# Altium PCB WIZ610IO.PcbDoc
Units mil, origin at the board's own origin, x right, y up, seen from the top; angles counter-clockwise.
Board outline 905.51 x 984.25 mil, 4 copper layers (Top Layer, MidLayer1, Mid-Layer 2, Bottom Layer); 42 components, 42 nets, 155 pads, 63 vias.
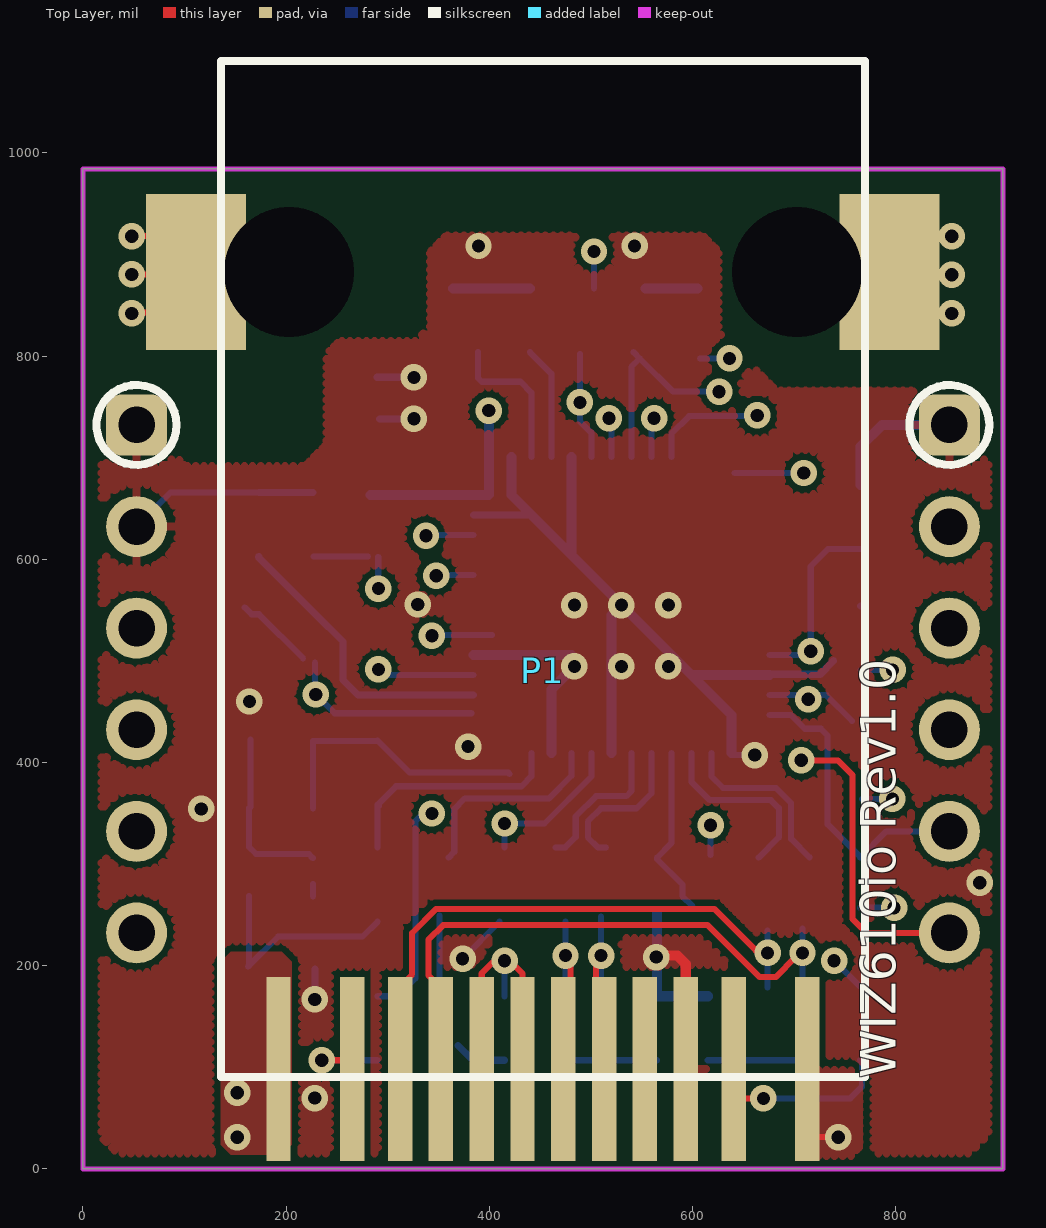
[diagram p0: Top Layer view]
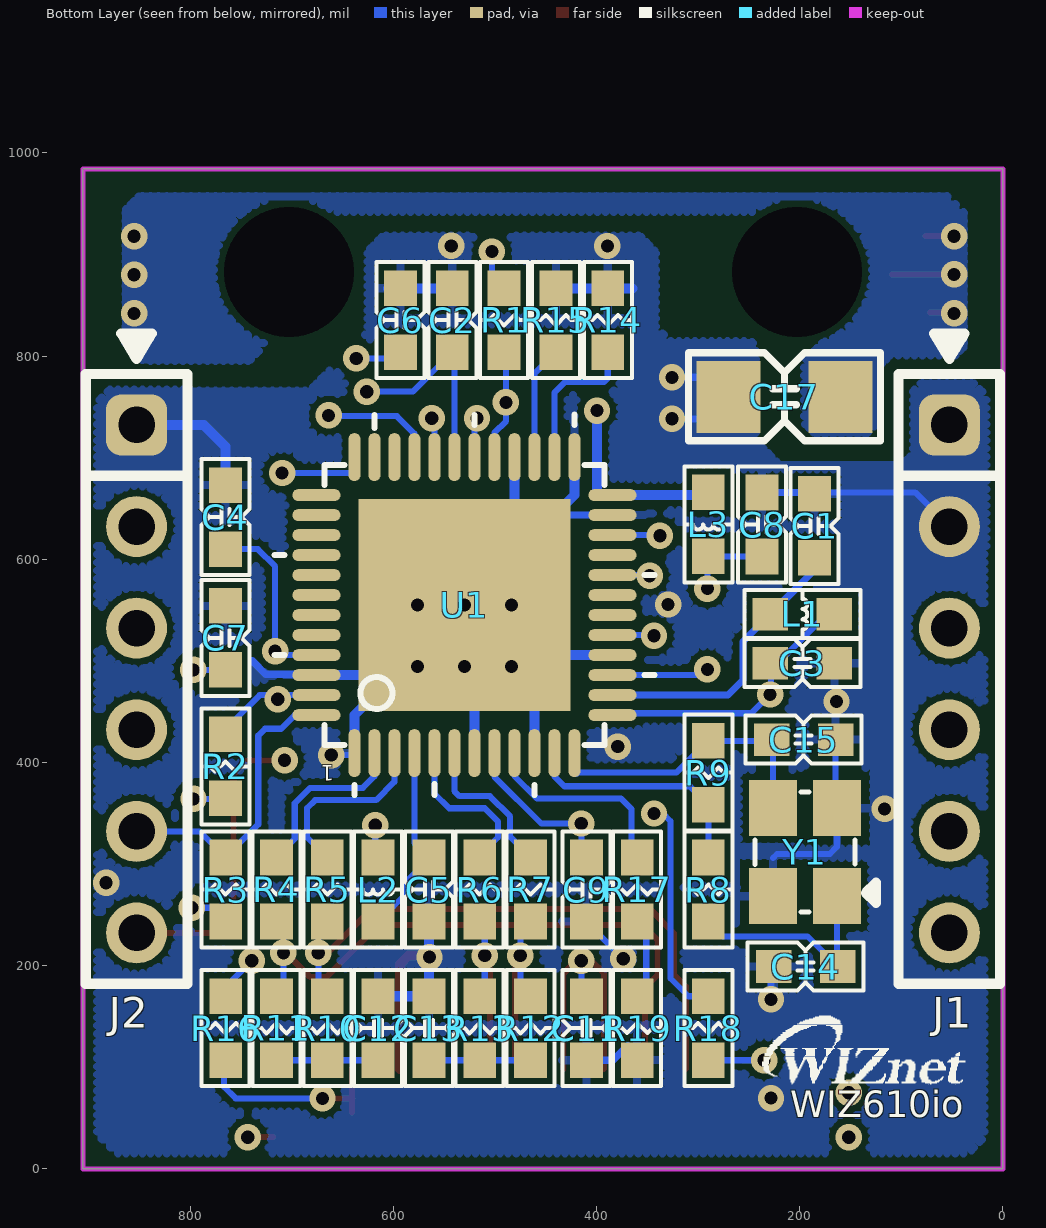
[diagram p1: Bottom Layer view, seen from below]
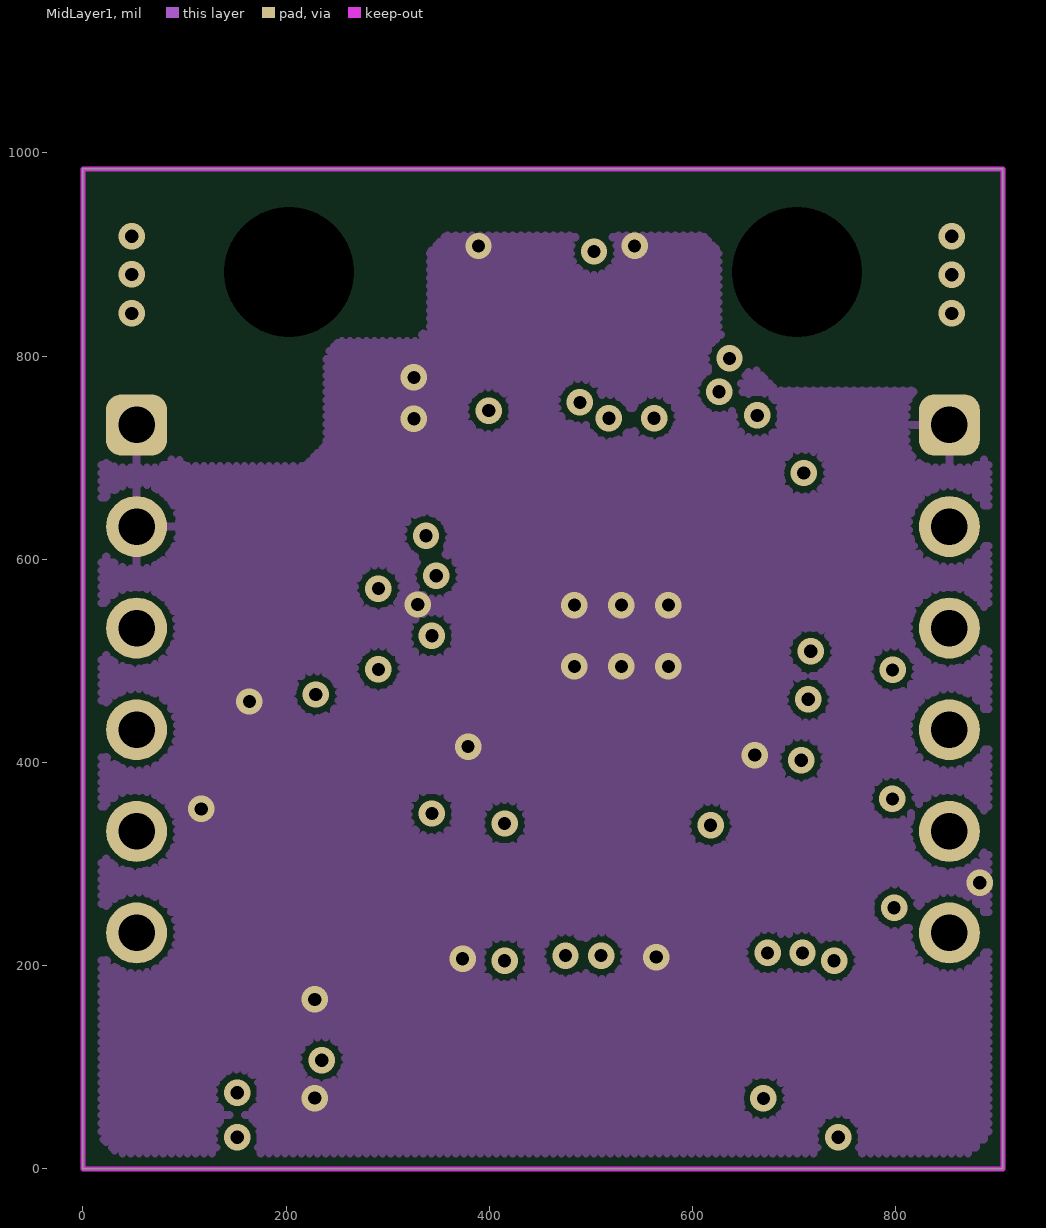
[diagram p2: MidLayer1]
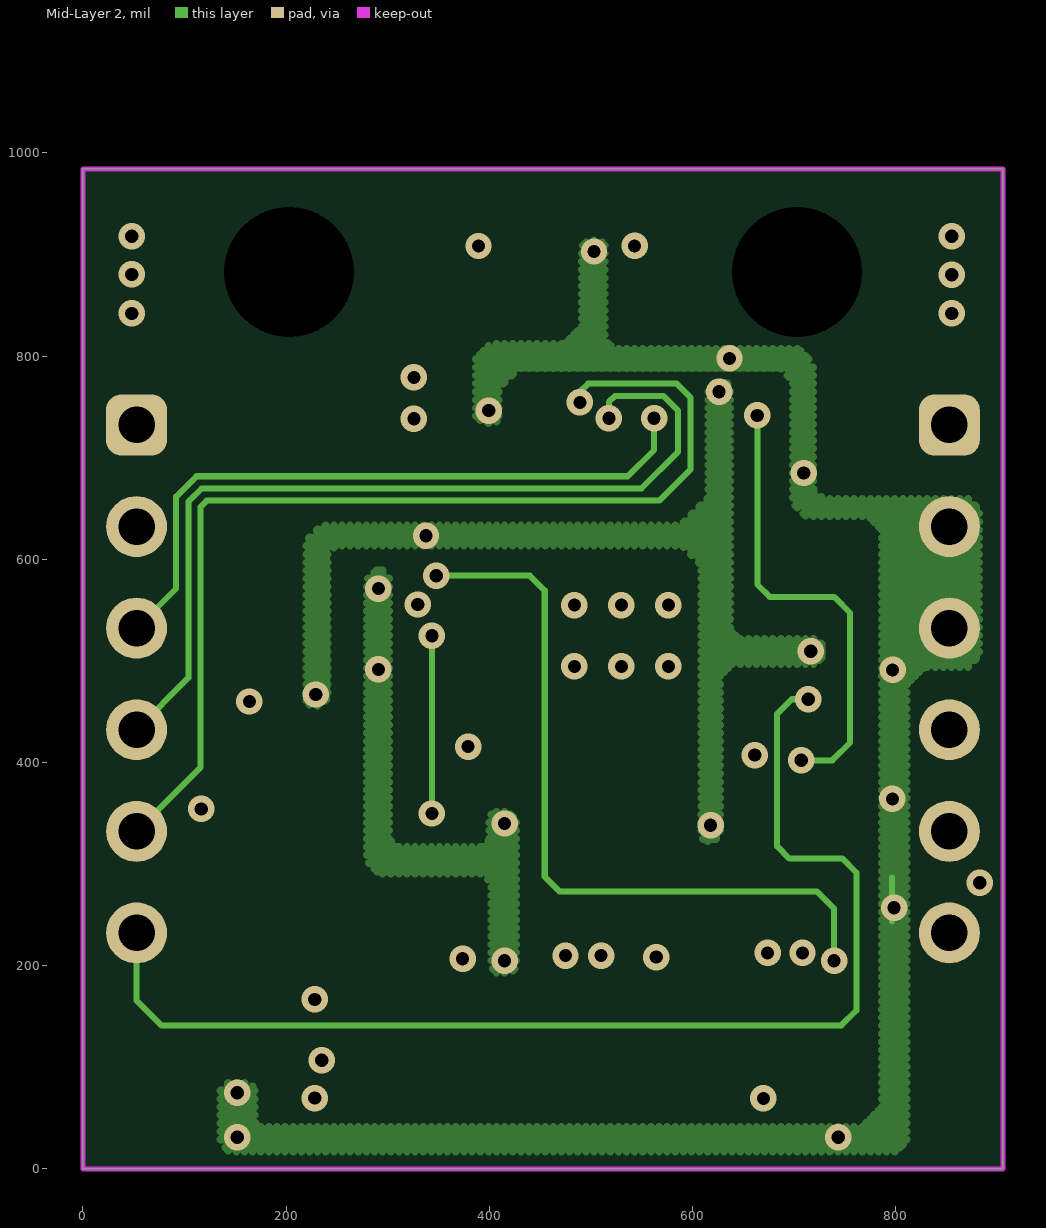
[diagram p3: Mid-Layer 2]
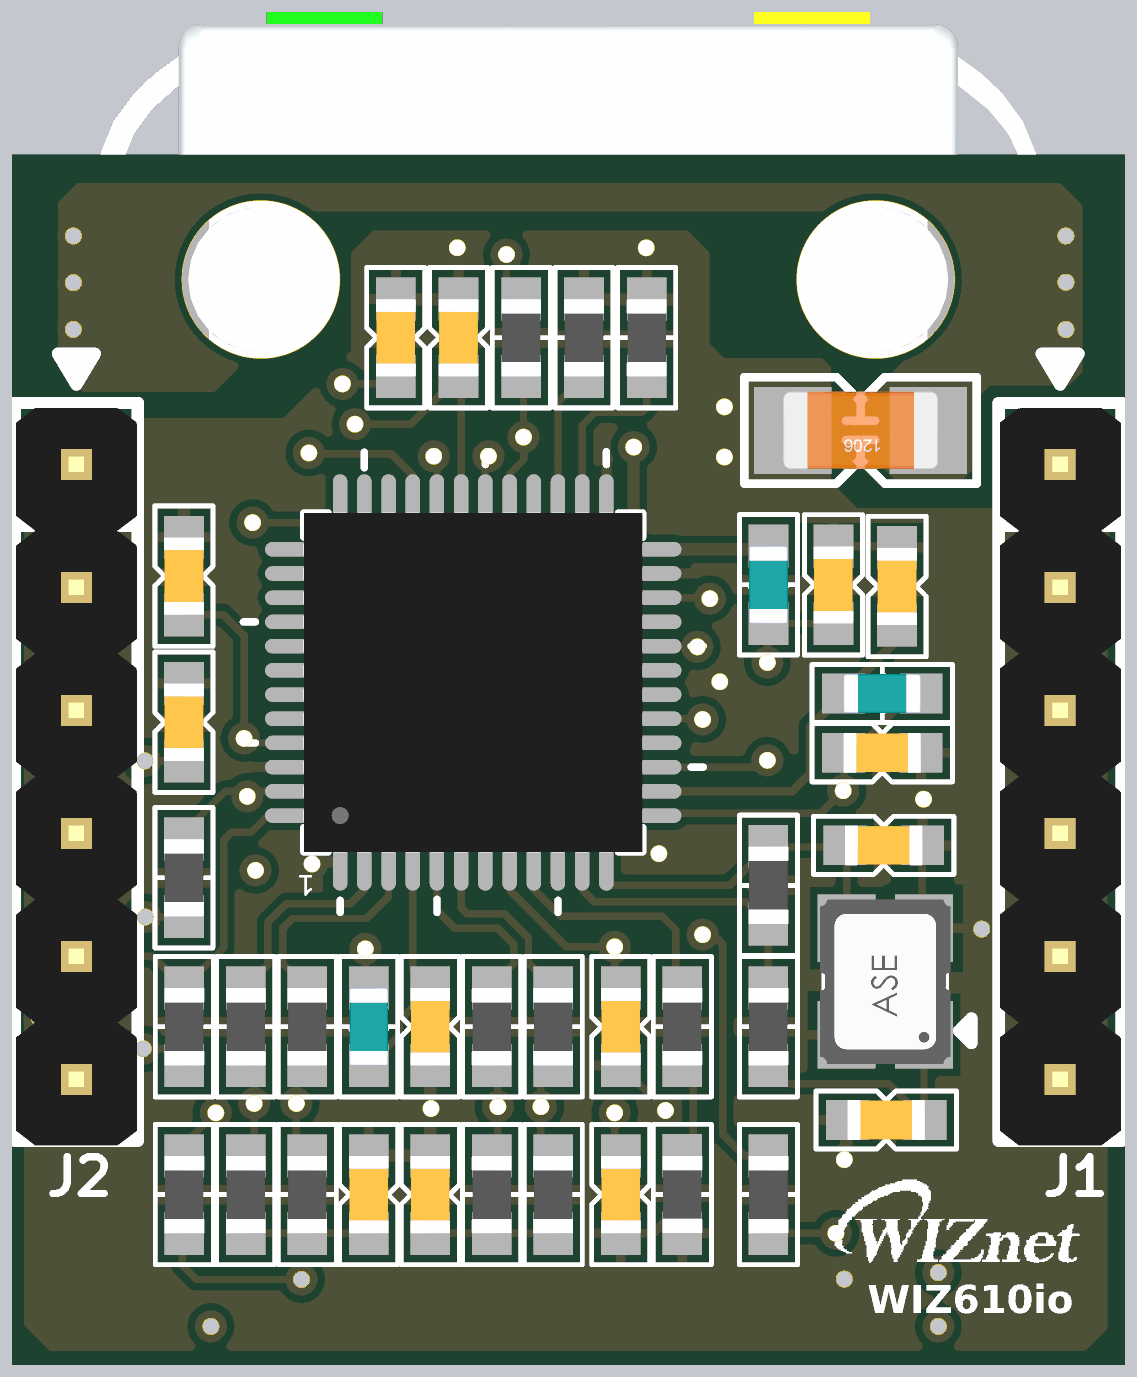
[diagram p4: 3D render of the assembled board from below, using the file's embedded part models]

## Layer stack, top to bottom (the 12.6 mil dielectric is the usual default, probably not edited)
Top Layer: signal copper 1.4
Dielectric: core 12.6, FR-4, Dk 4.8
MidLayer1: signal copper 1.4
Dielectric: prepreg 12.6, FR-4, Dk 4.8
Mid-Layer 2: signal copper 1.4
Dielectric: core 12.6, FR-4, Dk 4.8
Bottom Layer: signal copper 1.4

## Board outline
0,0 905.51,0 905.51,984.25 0,984.25

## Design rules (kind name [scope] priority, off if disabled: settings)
Clearance [All] p1: gap=6
DiffPairsRouting [All] p1: maxlimit=10 minlimit=10 mostfreqgap=10 maxuncoupledlength=500
PlaneClearance [All] p1: clearance=12
PlaneConnect [All] p1: planeconnectstyle=Direct reliefexpansion=20 reliefentries=4 reliefconductorwidth=10 reliefairgap=10
PolygonConnect PolygonConnect_1 [IsVia] p1: connectstyle=Direct reliefconductorwidth=10 reliefentries=4 polygonreliefangle="90 Angle" airgapwidth=10
PolygonConnect [All] p2: connectstyle=Relief reliefconductorwidth=8 reliefentries=4 polygonreliefangle="90 Angle" airgapwidth=8
RoutingVias [All] p1: holewidth=12 width=20 viastyle="Through Hole" minholewidth=12 minwidth=20 maxholewidth=28 maxwidth=50
SolderMaskExpansion [All] p1: expansion=0
Width [All] p1: maxlimit=100 minlimit=4 preferedwidth=10
25 further rules are at their usual default settings.

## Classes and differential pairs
differential pair RXO: +RXO_P -RXO_N
differential pair TXO: +TXO_P -TXO_N

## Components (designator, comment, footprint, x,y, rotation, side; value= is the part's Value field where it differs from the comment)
C1 "100nF" 0603-C 185.37,633.04 r270 bottom
C2 "100nF" 0603-C 541.97,835.34 r270 bottom
C3 "100nF" 0603-C 197.46,497.78 r0 bottom
C4 "100nF" 0603-C 765.31,641.51 r270 bottom
C5 "100nF" 0603-C 565,275 r90 bottom
C6 "100nF" 0603-C 592.97,835.34 r270 bottom
C7 "100nF" 0603-C 765.31,522.68 r270 bottom
C8 "100nF" 0603-C 237.11,634.28 r270 bottom
C9 "100nF" 0603-C 410,275 r90 bottom
C11 "1uF" 0603-C 410,138.5 r90 bottom
C12 "100nF" 0603-C 615,138.5 r270 bottom
C13 "100nF" 0603-C 565,138.5 r270 bottom
C14 "8pF" 0603-C 194.15,199.18 r180 bottom
C15 "8pF" 0603-C 196.24,422.5 r0 bottom
C17 "1nF/2kV" CAP-1206 215,760 r0 bottom
J1 "2.54mm 1x6 Pin Header DIP" IDC-1X6 52.76,732.28 r270 bottom locked
J2 "2.54mm 1x6 Pin Header DIP" IDC-1X6 852.76,732.28 r270 bottom locked
L1 "HH-1M1608-121JT" 0603-L 197.46,546 r180 bottom
L2 "HH-1M1608-121JT" 0603-L 615,275 r270 bottom
L3 "HH-1M1608-121JT" 0603-L 289.98,634.39 r270 bottom
P1 "BS-R250210" BS-R250210 452.76,590.55 r180 top locked
R1 "4.7K" 0603-R 490.96,835.34 r270 bottom
R2 "4.7K" 0603-R 765.31,396.17 r90 bottom
R3 "4.7k" 0603-R 765,275 r270 bottom
R4 "3.3R" 0603-R 715,275 r270 bottom
R5 "3.3R" 0603-R 665,275 r270 bottom
R6 "3.3R" 0603-R 515,275 r270 bottom
R7 "3.3R" 0603-R 465,275 r270 bottom
R8 "0R" 0603-R 290,275 r90 bottom
R9 "1M" 0603-R 290,390 r270 bottom
R10 "49.9R" 0603-R 665,138.5 r90 bottom
R11 "49.9R" 0603-R 715,138.5 r90 bottom
R12 "49.9R" 0603-R 465,138.5 r90 bottom
R13 "49.9R" 0603-R 515,138.5 r90 bottom
R14 "10K" 0603-R 388.96,835.34 r270 bottom
R15 "10K" 0603-R 439.96,835.34 r270 bottom
R16 "1K" 0603-R 765,138.5 r270 bottom
R17 "12K/1%" RES-0603 360,275 r90 bottom
R18 "1K" 0603-R 290,138.5 r270 bottom
R19 "300/1%" RES-0603 360,138.57 r90 bottom
U1 "W5100S" "WIZNET W5100S QFN" 530,555 r90 bottom locked
Y1 "25MHz" OSC-82J0626 194.9,311.74 r90 bottom

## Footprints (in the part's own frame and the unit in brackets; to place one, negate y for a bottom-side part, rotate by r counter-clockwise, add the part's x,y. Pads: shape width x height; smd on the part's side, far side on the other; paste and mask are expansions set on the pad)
0603-C [mm]
  rect 0.89x0.82 smd: 1(-0.8,0) 2(0.8,0)
  silkscreen extent -1.45,-0.6 1.45,0.6, body extent -0.93,-0.41 0.93,0.41, height 0.81
0603-L [mm]
  rect 0.89x0.82 smd: 1(-0.8,0) 2(0.8,0)
  silkscreen extent -1.45,-0.6 1.45,0.6, body extent -0.8,-0.4 0.8,0.4, height 0.95
0603-R [mm]
  rect 0.89x0.82 smd: 1(-0.8,0) 2(0.8,0)
  silkscreen extent -1.45,-0.6 1.45,0.6, body extent -0.82,-0.41 0.82,0.41, height 0.46
BS-R250210 [mm] "BS-R250210"
  rect 0.61x4.6 smd: L1(6.61,12.5) L2(4.77,12.5) L3(-4.77,12.5) L4(-6.61,12.5) R1(3.57,12.5) R2(2.55,12.5) R3(1.53,12.5) R4(0.51,12.5) R5(-0.51,12.5) R6(-1.53,12.5) R7(-2.55,12.5) R8(-3.57,12.5)
  rect 2.5x3.9 smd: S1(-8.67,-7.42) S2(8.67,-7.42)
  round 0 hole 3.25: ""(-6.35,-7.42) ""(6.35,-7.42)
  silkscreen extent -8.05,-12.7 8.05,12.7, body extent -9.75,-12.95 9.75,14.1, height 14.58
CAP-1206 [mm]
  rect 1.6x1.8 smd: 1(-1.4,0) 2(1.4,0)
  silkscreen extent -2.4,-1.1 2.4,1.1, body extent -1.6,-0.8 1.6,0.8, height 1
IDC-1X6 [mil]
  rrect50% 60x60 hole 36: 1(0,0)
  round 60 hole 36: 2(100,0) 3(200,0) 4(300,0) 5(400,0) 6(500,0)
  silkscreen extent -90,-50 550,50, body extent -46,-49 554,49, height 323
OSC-82J0626 [mm]
  rect 1.4x1.2 smd: 1(-1.1,-0.8) 2(1.1,-0.8) 3(1.1,0.8) 4(-1.1,0.8)
  silkscreen extent -1.5,-1.78 1.5,1.25, body extent -1.7,-1.35 1.7,1.35, height 1.06
RES-0603 [mm]
  rect 0.89x0.82 smd: 1(-0.8,0) 2(0.8,0)
  silkscreen extent -1.45,-0.6 1.45,0.6, body extent -0.82,-0.41 0.82,0.41, height 0.46
"WIZNET W5100S QFN" [mm] "WIZNET W5100S QFN"
  rect 5.3x5.3 smd: 0(0,0)
  oval 1.2x0.3 smd: 1(-3.7,2.75) 2(-3.7,2.25) 3(-3.7,1.75) 4(-3.7,1.25) 5(-3.7,0.75) 6(-3.7,0.25) 7(-3.7,-0.25) 8(-3.7,-0.75) 9(-3.7,-1.25) 10(-3.7,-1.75) 11(-3.7,-2.25) 12(-3.7,-2.75) 25(3.7,-2.75) 26(3.7,-2.25) 27(3.7,-1.75) 28(3.7,-1.25) 29(3.7,-0.75) 30(3.7,-0.25) 31(3.7,0.25) 32(3.7,0.75) 33(3.7,1.25) 34(3.7,1.75) 35(3.7,2.25) 36(3.7,2.75)
  oval 0.3x1.2 smd: 13(-2.75,-3.7) 14(-2.25,-3.7) 15(-1.75,-3.7) 16(-1.25,-3.7) 17(-0.75,-3.7) 18(-0.25,-3.7) 19(0.25,-3.7) 20(0.75,-3.7) 21(1.25,-3.7) 22(1.75,-3.7) 23(2.25,-3.7) 24(2.75,-3.7) 37(2.75,3.7) 38(2.25,3.7) 39(1.75,3.7) 40(1.25,3.7) 41(0.75,3.7) 42(0.25,3.7) 43(-0.25,3.7) 44(-0.75,3.7) 45(-1.25,3.7) 46(-1.75,3.7) 47(-2.25,3.7) 48(-2.75,3.7)
  silkscreen extent -4.75,-4.75 4.77,4.75, body extent -3.51,-3.51 3.51,3.51, height 0.78

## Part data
C1 C2 C3 C4 C5 C6 C7 C8 C9 C11 C12 C13 C14 C15: library part CAP-0603, "Ceramic CAP 0603(1608)"
C17: library part CAP-1808, "Ceramic CAP 1808(4520)"
L1 L2 L3: library part IND-0603, "Inductor 0603(1608)"
R1 R2 R3 R4 R5 R6 R7 R8 R9 R10 R11 R12 R13 R14 R15 R16 R17 R18 R19: library part RES-0603, "RES0603"
U1: "WIZnet Hardwired TCP/IP Chip"
Y1: library part OSC-82J0626-25MHz, "X-tal 25MHz,3.2x2.5 SMD, CL=18pF"

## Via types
v1: diameter 26, hole 13, Top Layer to Bottom Layer, tented both sides, 63 vias

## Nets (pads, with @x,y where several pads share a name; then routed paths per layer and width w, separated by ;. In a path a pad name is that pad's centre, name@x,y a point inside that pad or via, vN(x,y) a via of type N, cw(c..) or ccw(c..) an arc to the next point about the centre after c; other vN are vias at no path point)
1V2A: C5.2 L2.2 U1.4 | length 171.2
  Bottom Layer w6: U1.4 579.21,320.71 C5.2 565,305 590,280 590,268.5 L2.2@600,258.5
1V2D: C2.2 C3.2 C4.2 L1.2 L2.1 U1.13 U1.22 U1.31 U1.45 | length 717.3
  Bottom Layer w6: L1.2@159.19,552.77 L1.2 173.22,546 C3.2@216.75,502.48 ; C3.2@228.26,498.65 228.26,467.87 247.63,448.5 U1.13@382.57,448.5 ; v1@337.54,623.9 U1.22 ; U1.31 539.84,789.35 C2.2@548.15,797.66 ; C2.2 C2.2@548.15,797.66 ; v1@613.56,765 580.82,765 C2.2@548.15,797.66 ; L2.1@617.76,309.26 v1(617.76,338.32) ; U1.45 712.72,505.79 v1(716.39,509.45) 716.39,593.11 733.29,610.02 C4.2
  other v1: 229.18,466.94 337.64,623.12 626.17,765
1V2O: C1.2 L1.1 U1.14 | length 290.2
  Bottom Layer w7: C1.2@173.07,602.62 173.07,601.89 L1.1 255.98,518.98 255.98,481.19 270.75,466.42 U1.14
3V3A: C8.2 C9.2 C11.2 L3.2 P1.R3 P1.R4 U1.8 U1.15 | length 607.7
  Top Layer w6: P1.R3 392.52,192.52 405,205 v1(415,205) 420,205 432.68,192.32 P1.R4
  Bottom Layer w6: C8.2@227.22,602.89 L3.2@280.37,602.89 ; v1@290.66,571.18 L3.2@290.66,602.22 ; v1(290.83,491.68) 296.43,486.11 U1.15 ; C11.2@415,170 v1(415,205) v1@417.89,205 ; C9.2@415,316.5 v1(415,340) 454.31,340 500.47,386.16 U1.8
  other v1: 290.83,571.18
3V3D: C6.2 C7.2 J2.2 J2.3 L3.1 P1.L1 P1.L4 R1.1 R2.1 R3.2 U1.24 U1.36 | length 490.6
  Top Layer w6: P1.L4@718.47,31.28 v1(743.34,31.28)
  Mid-Layer 2 w6: 796.44,243.48 796.44,286.66
  Bottom Layer w6: R1.1@502.99,866.5 v1(502.99,903.01) ; C6.2@607.55,797.79 v1(636.41,797.79) ; U1.36@641.44,684.96 v1(709.47,684.96) ; R3.2@764.84,257.09 v1(798.39,257.09) ; C7.2 v1(796.89,491.19) ; R2.1@766.77,364.22 v1(796.71,364.22)
  Bottom Layer w10: L3.1@282.99,663.27 U1.24 399.1,663.27 399.71,663.88 v1@399.71,741.01
  other v1: 151.8,31.28 151.82,75.02 399.51,746.39
ACTN: R16.1 U1.20 | length 815
  Mid-Layer 2 w6: v1(347.79,583.95) 439.86,583.95 454.51,569.3 454.51,287.69 469,273.2 722.4,273.2 739.38,256.23 v1(739.38,205)
  Bottom Layer w6: v1@349.06,584.53 U1.20 ; v1(739.38,205) R16.1@765,179.37
CHGND: C17.1 P1.S1 P1.S2 | length 112.6
  Top Layer w6: v1@48.03,842.8 P1.S2@71.54,842.8 ; v1(48.03,880.45) P1.S2@109.19,880.45 ; v1(48.03,918.09) P1.S2@76.01,918.09
  other v1: 48.03,842.06 855.18,842.06 855.18,880.07 855.18,918.09
D0: U1.37
D1: U1.38
D2: U1.39
D3: U1.40
D4: U1.41
D5: U1.42
D6: U1.43
D7: U1.44
GND: C1.1 C2.1 C3.1 C4.1 C5.1 C6.1 C7.1 C8.1 C9.1 C11.1 C12.1 C13.1 C14.1 C15.1 C17.2 J1.1 J1.2 J2.1 P1.R8 R14.1 R15.1 R19.1 U1.0 U1.1 U1.7 U1.10 U1.16 U1.23 U1.25 U1.28 U1.46 Y1.2 Y1.4 | length 2127.6
  Top Layer w10: v1@565,210 585,210 593.31,201.69 P1.R8
  Bottom Layer w6: J1.2 86.36,665.88 C1.1@185.37,665.88 ; Y1.2 163.4,317.09 170.5,310 222.4,310 226.4,306 ; Y1.2@164.74,356.39 C15.1 ; Y1.4 Y1.4@226.4,280.51 ; v1(373.67,206.91) 410,243.24 C9.1 ; U1.1@640.23,407.37 v1(661.15,407.37)
  Bottom Layer w7: C1.1@173.07,665.88 C8.1@226.22,665.88 ; v1(228.25,166.89) C14.1@228.25,196.57 ; C17.2@289.37,779.25 v1@317.11,779.25 ; C17.2@292,738.12 v1@317.11,738.12 ; R19.1@369.31,121.61 383.91,107.01 C11.1@415,107.01 ; U1.23 U1.0@441.41,643.59 ; U1.46 676.52,486.95 725.7,486.95 738.89,500.13 ; C7.1 C7.1@766.02,554.18
  Bottom Layer w10: 364.47,866.5 R15.1@439.96,866.5 ; U1.16 U1.0@480.79,505.79 ; U1.25 421.73,663.27 441.41,643.59 U1.0@480.79,604.21 ; U1.10 461.1,472.03 v1(483.71,494.63) ; U1.28 U1.0@480.79,604.21 ; U1.7 U1.0@520.16,545.16 ; C2.1@554,866.5 C6.1@605,866.5 ; C5.1@565,253.5 C5.1 C13.1 C12.1 ; U1.1 638.27,446.73 U1.0@598.89,486.11 ; U1.46 U1.0@598.89,486.11 ; C4.1 765.31,711 786.6,732.28 J2.1 ; U1.0@480.79,604.21 v1(530,555) U1.0@598.89,486.11
  other v1: 228.25,69.76 564.37,208.49 882.75,281.59 116.47,354.39 379.09,415.74 163.8,460.04 530,494.63 576.29,494.63 483.71,555 576.29,555 329.52,555.54 325.76,738.31 325.76,779.11 389.35,908.44 543,908.52
INTN: J1.6 R2.2 U1.47 | length 1274.9
  Mid-Layer 2 w6: J1.6 52.76,165.74 77.18,141.32 746.48,141.32 761.38,156.21 761.38,291.74 747.73,305.39 695.32,305.39 683.15,317.55 683.15,447.8 697.69,462.34 v1(713.8,462.34)
  Bottom Layer w6: U1.47 731.62,466.42 R2.2@757.14,440.89
LINKN: R18.1 U1.17 | length 444.7
  Top Layer w6: v1(343.48,524.89) v1@343.48,525.48
  Mid-Layer 2 w6: v1(343.48,349.87) v1(343.48,524.89)
  Bottom Layer w6: R18.1 309.5,170 327.22,187.72 327.22,342.22 v1@334.86,349.87 ; v1@343.48,525.48 U1.17 U1.17@402.71,525.48
MISO: J2.6 U1.33 | length 865.3
  Top Layer w6: v1(707.07,402.15) 743.09,402.15 757.35,387.9 757.35,246.12 771.19,232.28 v1(852.76,232.28)
  Mid-Layer 2 w6: v1(663.74,741.62) 663.74,575.22 675.91,563.05 739.32,563.05 755.17,547.2 755.17,419.72 737.6,402.15 v1(707.07,402.15)
  Bottom Layer w6: U1.33 579.21,723.58 596.54,740.9 v1@663.03,740.9
MODE1: R14.2 U1.26 | length 147.3
  Bottom Layer w6: R14.2 388.96,778.37 392.5,774.83 430.72,774.83 441.42,764.13 U1.26
MODE2: R15.2 U1.27 | length 111.9
  Bottom Layer w6: R15.2 461.1,782.71 U1.27
MOSI: J1.3 U1.32 | length 700.1
  Mid-Layer 2 w6: J1.3 91.76,571.28 91.76,661.63 111.87,681.74 536.24,681.74 562.13,707.62 v1(562.13,738.96)
  Bottom Layer w6: U1.32 v1@559.53,734.53
NetC12_2: C12.2 R10.1 R11.1 | length 100
  Bottom Layer w6: C12.2 R10.1 R11.1
NetC13_2: C13.2 R12.1 R13.1 | length 100
  Bottom Layer w6: R12.1 R13.1 C13.2
NetC14_2: C14.2 R8.1 Y1.1 | length 214.2
  Bottom Layer w6: C14.2 C14.2@163.4,199.94 ; Y1.1 C14.2@163.4,199.94 ; R8.1 275.26,228.76 192.23,228.76 C14.2@163.4,199.94
NetC15_2: C15.2 R9.1 U1.12 Y1.3 | length 273.4
  Bottom Layer w6: Y1.3 226.4,421.16 289.67,421.16 R9.1 321.5,390 418.71,390 U1.12@420,388.71
NetP1_L2: P1.L2 R18.2 | length 76.2
  Top Layer w6: v1(235.11,107.01) P1.L2@256.38,107.01
  Bottom Layer w6: v1(235.11,107.01) R18.2
NetP1_L3: P1.L3 R16.2 | length 200.9
  Top Layer w6: P1.L3@640.1,69.47 v1(669.72,69.47) ; P1.L3@640.55,55.64 P1.L3
  Bottom Layer w6: v1(669.72,69.47) 755.27,69.47 766.68,80.88 766.68,105.33 R16.2
NetR4_1: R4.1 U1.2 | length 173.2
  Bottom Layer w6: U1.2 618.58,386.42 630,375 681.97,375 697,359.97 697,325 715,307 R4.1
NetR5_1: R5.1 U1.3 | length 181.9
  Bottom Layer w6: U1.3 598.9,381.1 617,363 677,363 685,355 685,326.5 R5.1
NetR6_1: R6.1 U1.5 | length 151.4
  Bottom Layer w6: R6.1@515,316.5 506.82,316.5 497.09,326.23 497.09,342.09 510,355 545,355 559.53,369.53 U1.5
NetR7_1: R7.1 U1.6 | length 147.1
  Bottom Layer w6: R7.1@465,316.5 474.7,316.5 485.09,326.88 485.09,347.06 505.03,367 535,367 539.84,371.84 U1.6
NetR8_2: R8.2 R9.2 U1.11 | length 229
  Bottom Layer w6: R8.2@290,316.5 R9.2 308.2,376.71 431.71,376.71 441.42,386.42 U1.11 ; R9.2@290.5,356.5 R9.2@291.25,357.25
NetR17_1: R17.1 R19.2 | length 73.4
  Bottom Layer w6: R19.2@351.06,175.94 R17.1@351.06,249.39
NetR17_2: R17.2 U1.9 | length 201.3
  Bottom Layer w6: R17.2 365.48,311.97 365.48,354.21 375.98,364.71 458.74,364.71 480.79,386.75 U1.9
RSTN: J2.5 R3.1 U1.48 | length 297.4
  Bottom Layer w6: U1.48 697.08,446.74 710.52,433.3 726.24,433.3 733.01,426.53 733.01,339.15 765,307.16 R3.1 790.79,332.28 J2.5
RXO_N: P1.R6 R6.2 R13.2 | length 179.2
  Top Layer w6: P1.R6@505,106.42 505,205 v1(510,210)
  Bottom Layer w6: R13.2@510,175 v1(510,210) R6.2@510,248.5
RXO_P: P1.R5 R7.2 R12.2 | length 173
  Top Layer w6: P1.R5 480,105.59 v1@480,205
  Bottom Layer w6: R12.2@475,180 v1(475,210) R7.2@475,243.5
SCLK: J1.4 U1.30 | length 916.9
  Mid-Layer 2 w6: J1.4 103.76,483.28 103.76,656.66 116.84,669.74 549.69,669.74 585.86,705.91 585.86,746.34 571.24,760.96 523.71,760.96 517.64,754.9 v1(517.64,738.96)
  Bottom Layer w6: U1.30 v1@520.16,736.45
SCSN: J1.5 R1.2 U1.29 | length 1148.2
  Mid-Layer 2 w6: J1.5 115.76,395.28 115.76,651.69 121.81,657.74 567.3,657.74 597.86,688.29 597.86,759.46 584.35,772.96 497.26,772.96 489.16,764.87 v1(489.16,754.49)
  Bottom Layer w6: v1(489.16,754.49) v1@489.16,754.59 ; R1.2@489.16,802.05 v1@489.16,754.59 ; U1.29 500.47,724.72 489.07,736.13 489.07,754.49 v1@489.16,754.59
TXO_N: P1.R2 R4.2 R11.2 | length 589.4
  Top Layer w6: P1.R2 352.36,178.17 340,190.53 340,225.59 354.41,240 614.78,240 665.96,188.82 681.91,188.82 v1@701.79,208.7
  Bottom Layer w6: R11.2@708.21,176.79 v1(708.21,212.59) R4.2@708.21,236.72
TXO_P: P1.R1 R5.2 R10.2 | length 559.5
  Top Layer w6: P1.R1 312.2,179.48 324,191.27 324,232.22 347.78,256 621.41,256 v1@662.23,215.18
  Bottom Layer w6: R10.2@673.86,178.86 v1(673.86,212.59) R5.2@673.86,234.65
pads on no net: J2.4 P1. P1.R7 U1.18 U1.19 U1.21 U1.34 U1.35
copper on no net:
  other v1: 702.76,882.68

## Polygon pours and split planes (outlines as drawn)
GND on Bottom Layer "Mid-Layer 2-No Net" (hatched 90Degree grid 0 track 8, remove dead copper, pour order 43): 891.46,685 891.46,754.81 879.36,766.91 805.86,766.91 792.2,753.26 792.2,703.05 810.28,684.98
CHGND on Bottom Layer "Mid-Layer 2-No Net" (hatched 90Degree grid 0 track 8, remove dead copper, pour order 42): 120.91,780.79 120.91,736.89 134.62,723.17 184.75,723.17 195.98,734.4 195.98,794.93 177.9,813 177.9,915.1 199.47,936.66 204.77,941.96 247,941.96 670.53,941.96 688.4,924.1 725.01,887.49 725.01,812.13 741.83,795.31 779.35,795.31 846.03,795.31 863.73,813 863.73,943.86 850.25,957.33 54.76,957.33 38.42,941 38.42,809.03 47,800.45 111.32,800.45 120.92,790.84
GND on Bottom Layer "Mid-Layer 2-No Net" (hatched 90Degree grid 0 track 8, remove dead copper, pour order 41): 18.21,605.04 16.45,606.8 16.45,740.41 16.45,761.11 28.67,773.33 80.54,773.33 88.27,765.6 88.27,704.31 99.58,693 219.62,693 231,704.38 242.9,716.28 242.9,741.66 242.9,809.68 247.93,814.71 327.51,814.71 337.22,805 337.22,705.05 326.7,694.52 320.71,688.54 195.76,688.54 126.93,688.54 108.72,670.33 108.72,601 88.72,581 34.21,581 18.21,597
GND on Bottom Layer "Mid-Layer 2-No Net" (hatched 90Degree grid 0 track 8, remove dead copper, pour order 40): 28.98,768.29 77.01,768.29 87,758.3 87,705.58 100.96,691.62 218.23,691.62 234.04,707.42 239.8,713.18 239.8,757 239.8,802.17 252.33,814.71 327.61,814.71 341.74,828.85 341.74,902.87 357.55,918.68 609.97,918.68 625.36,903.29 625.36,823.44 676.93,771.88 682.81,766 831,766 882.47,766 891.46,757 891.46,34.1 872.8,15.43 34.01,15.43 18.21,31.23 18.21,757.51 28.98,768.29
GND on Bottom Layer "Mid-Layer 2-No Net" (hatched 90Degree grid 0 track 8, remove dead copper, pour order 37): 239.67,727.7 256.45,707.85 300.61,707.85 324.88,707.85 339.34,724.95 339.34,802.5 329.01,814.71 247.93,814.71 239.93,805.25
GND on Top Layer "Mid-Layer 2-No Net" (hatched 90Degree grid 0 track 8, remove dead copper, pour order 39): 28.98,768.29 77.01,768.29 87,758.3 87,705.58 100.96,691.62 218.23,691.62 234.04,707.42 239.8,713.18 239.8,757 239.8,802.17 252.33,814.71 327.61,814.71 341.74,828.85 341.74,902.87 357.55,918.68 609.97,918.68 625.36,903.29 625.36,823.44 676.93,771.88 682.81,766 831,766 882.47,766 891.46,757 891.46,34.1 872.8,15.43 34.01,15.43 18.21,31.23 18.21,757.51 28.98,768.29
3V3D on Top Layer "Keep-Out Layer-No Net" (solid, remove dead copper, pour order 29): 145.65,213.77 135.65,203.77 135.65,23.77 145.65,13.77 195.65,13.77 205.65,23.77 205.65,203.77 195.65,213.77
3V3D on Top Layer "Mid-Layer 2-No Net" (hatched 90Degree grid 0 track 8, remove dead copper, pour order 35): 713.24,97.37 755.37,97.37 764.29,88.44 764.29,21.47 755.52,12.71 716.07,12.71 707.31,21.47 707.31,91.43 713.24,97.37
3V3D on Mid-Layer 2 "Mid-Layer 2-No Net" (hatched 90Degree grid 0 track 8, remove dead copper, pour order 36): 506.37,788.42 429.16,788.42 415.9,775.16 409.04,768.3 409.04,737.7 405.61,734.27 393.74,734.27 387.14,740.86 387.14,755.37 387.14,797.85 401.39,812.1 474.42,812.1 491.33,829
1V2D on Mid-Layer 2 "Mid-Layer 2-No Net" (hatched 90Degree grid 0 track 8, remove dead copper, pour order 34): 612.46,322.87 620.87,322.87 626.95,328.95 626.95,485.05 639.1,497.2 720.89,497.2 727.43,503.74 727.43,516.07 721.75,521.75 645.25,521.75 636.61,530.39 636.61,770.94 634.21,773.34 621.26,773.34 615.75,767.83 615.75,660.78 598.5,643.54 587.97,633 333.86,633 234.59,633 222.14,620.55 220.22,618.64 220.22,527.02 220.22,460.01 223.84,456.39 233.67,456.39 240.88,463.59 240.88,605.78 248.9,613.81 589.64,613.81 608.84,594.6 608.84,326.33 612.35,322.81
3V3D on Mid-Layer 2 "Mid-Layer 2-No Net" (hatched 90Degree grid 0 track 8, remove dead copper, pour order 33): 871.56,659.54 728.57,659.54 720.92,667.19 718.74,669.37 718.74,704.04 718.74,792.34 706.53,804.55 703.91,807.17 628.04,807.17 522.29,807.17 513.35,816.11 513.35,909.43 509.21,913.57 497,913.57 491.33,907.9 491.33,803.46 500.27,794.53 506.37,788.42 651.8,788.42 686.25,788.42 694.32,780.35 698.9,775.77 698.9,691.61 698.9,655.42 711.54,642.77 772.81,642.77 786.59,629 787.64,627.95 803.77,627.95
3V3D on Mid-Layer 2 "Mid-Layer 2-No Net" (hatched 90Degree grid 0 track 8, remove dead copper, pour order 32): 810.54,172.94 810.54,476.66 828.02,494.15 870.86,494.15 881.75,505.03 881.75,649.36 871.56,659.54 800.28,659.54 786.59,645.84 786.59,60.9 767,41.32 779.32,29 810.54,29
3V3D on Mid-Layer 2 "Mid-Layer 2-No Net" (hatched 90Degree grid 0 track 8, remove dead copper, pour order 31): 788.77,173 788.77,55.08 775,41.32 173.7,41.32 168.89,46.12 168.89,79.21 163.67,84.43 142.69,84.43 135.26,77 135.26,26.06 143.93,17.39 800.38,17.39 810.54,27.55 810.54,172.94 810.47,173
3V3A on Mid-Layer 2 "Mid-Layer 2-No Net" (hatched 90Degree grid 0 track 8, remove dead copper, pour order 30): 289.01,589.14 279.63,579.77 279.63,562.11 279.63,303.07 291.84,290.86 393.02,290.86 398.68,285.19 402.39,281.49 402.39,215.64 402.39,198.2 409.59,191 418.68,191 426.34,198.66 426.34,343.67 418.74,351.26 404.35,351.26 399.99,346.9 399.99,324.01 392.58,316.59 309.07,316.59 301.22,324.44 301.22,583.91 296.21,588.92
GND on MidLayer1 "Mid-Layer 2-No Net" (hatched 90Degree grid 0 track 8, remove dead copper, pour order 38): 28.98,768.29 77.01,768.29 87,758.3 87,705.58 100.96,691.62 218.23,691.62 234.04,707.42 239.8,713.18 239.8,757 239.8,802.17 252.33,814.71 327.61,814.71 341.74,828.85 341.74,902.87 357.55,918.68 609.97,918.68 625.36,903.29 625.36,823.44 676.93,771.88 682.81,766 831,766 882.47,766 891.46,757 891.46,34.1 872.8,15.43 34.01,15.43 18.21,31.23 18.21,757.51 28.98,768.29

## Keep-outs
Keep-Out Layer:
  the board outline again, w5

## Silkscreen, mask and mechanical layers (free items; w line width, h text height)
Top Overlay:
  text "WIZ610io Rev1.0" at 811.61,89.24 h60 r90
Bottom Overlay:
  drawing of 390 lines, arcs and shapes, not listed
  text "WIZ610io" at 209.46,42.19 h45
Mechanical 2:
  the board outline again, w5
